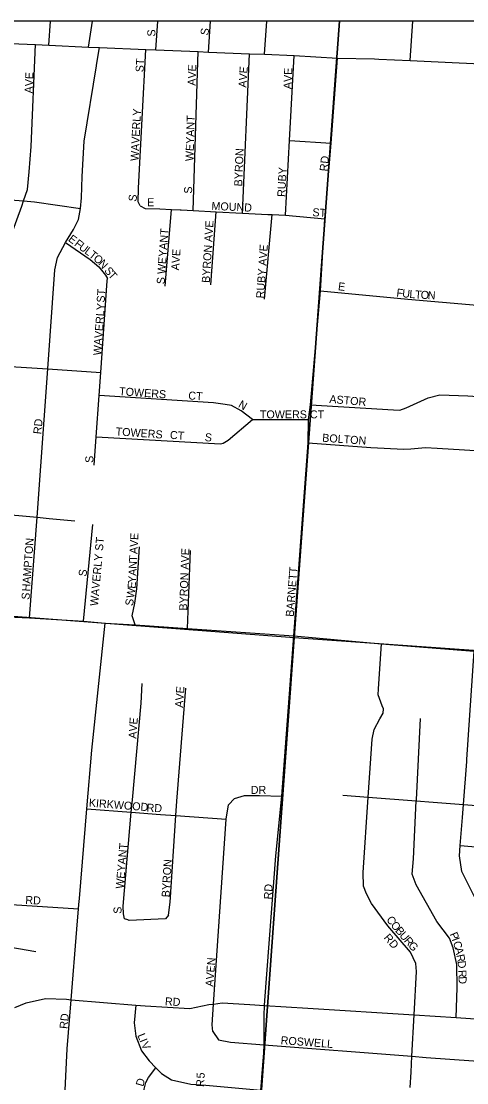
# Model space of a CAD drawing. Extents: x 0 to 34, y 0 to 22.
# Drawn here: x 5.068 to 5.595, y 19.645 to 20.9 of the extents above; entities that cross this region are included whole.
import ezdxf

# ---------------------------------------------------------------- set-up
doc = ezdxf.new("R2010")
doc.units = 0
for name, color, linetype in [('GM_X_City_Street', 7, 'Continuous'), ('GM_X_City_Street_Text', 7, 'Continuous'), ('GM_X_Section', 7, 'Continuous'), ('GM_X_Township', 7, 'Continuous'), ('GM_X_US_Route', 7, 'Continuous')]:
    doc.layers.add(name, color=color, linetype=linetype)

msp = doc.modelspace()

# ---------------------------------------------------------------- linework, layer by layer
at = {"layer": 'GM_X_City_Street'}
for points in [[(5.1011, 20.8716), (5.103, 20.9)], [(5.148, 20.8695), (5.1527, 20.9)], [(5.2275, 20.8662), (5.2299, 20.9)], [(5.2896, 20.8636), (5.2922, 20.9)], [(5.3558, 20.8609), (5.3585, 20.9)], [(5.5281, 20.8535), (5.5313, 20.9)], [(5.0237, 20.292), (5.0238, 20.2924), (5.0259, 20.3188), (5.04, 20.4931), (5.0489, 20.6036), (5.0507, 20.6286), (5.0558, 20.6448), (5.069, 20.6813), (5.0712, 20.6875), (5.076, 20.7008), (5.0777, 20.722), (5.0801, 20.7519), (5.0855, 20.8723)], [(5.1574, 20.8479), (5.1608, 20.8689)], [(5.2092, 20.6818), (5.2067, 20.6864), (5.2072, 20.7027), (5.2158, 20.8667)], [(5.2716, 20.6761), (5.2775, 20.8641)], [(5.3299, 20.6731), (5.3384, 20.8616)], [(5.3806, 20.6705), (5.3854, 20.7588), (5.391, 20.8595)], [(5.3905, 20.173), (5.4075, 20.4012), (5.4079, 20.4289), (5.4104, 20.4465), (5.4222, 20.5812), (5.4271, 20.6663), (5.4348, 20.7558), (5.4421, 20.8564)], [(5.0784, 20.1943), (5.0873, 20.3133), (5.0998, 20.4888), (5.1081, 20.6061), (5.1112, 20.6204), (5.1209, 20.6382), (5.1303, 20.6537), (5.136, 20.6657), (5.1386, 20.6785), (5.1397, 20.691), (5.1405, 20.7164), (5.1428, 20.7581), (5.1573, 20.8472), (5.1574, 20.8479)], [(5.3854, 20.7588), (5.4348, 20.7558)], [(5.0001, 20.6928), (5.0031, 20.6926), (5.0712, 20.6875), (5.0843, 20.6865), (5.1386, 20.6785)], [(5.2092, 20.6818), (5.2148, 20.6786), (5.2322, 20.6781), (5.2459, 20.6774), (5.2563, 20.6768)], [(5.2387, 20.5868), (5.2459, 20.6774)], [(5.2563, 20.6768), (5.2576, 20.6768), (5.2716, 20.6761), (5.2988, 20.6747), (5.3299, 20.6731), (5.3599, 20.6716)], [(5.2925, 20.5882), (5.2988, 20.6747)], [(5.3561, 20.5712), (5.3651, 20.6713)], [(5.3599, 20.6716), (5.3651, 20.6713), (5.3806, 20.6705), (5.4271, 20.6663)], [(5.1209, 20.6382), (5.1498, 20.6183), (5.1601, 20.6095), (5.1682, 20.5998), (5.1703, 20.5959)], [(5.1548, 20.375), (5.1572, 20.4084), (5.1606, 20.4572), (5.1626, 20.4846), (5.1702, 20.5929), (5.1703, 20.5959)], [(5.4222, 20.5812), (5.5255, 20.5713), (5.6571, 20.5599)], [(4.9121, 20.5032), (4.978, 20.498), (5.04, 20.4931), (5.0559, 20.4918), (5.0998, 20.4888), (5.1626, 20.4846)], [(5.3417, 20.4289), (5.3284, 20.4391), (5.3168, 20.4455), (5.3093, 20.4469), (5.2957, 20.4488), (5.1606, 20.4572)], [(5.4104, 20.4465), (5.5085, 20.4404), (5.516, 20.4402), (5.5233, 20.4426), (5.5494, 20.4548), (5.5632, 20.4582), (5.5961, 20.4568), (5.682, 20.4509), (5.694, 20.4472)], [(5.1572, 20.4084), (5.304, 20.4001), (5.3072, 20.4009), (5.3131, 20.4044), (5.3417, 20.4289)], [(5.3417, 20.4289), (5.4079, 20.4289)], [(5.4075, 20.4012), (5.4814, 20.396), (5.5204, 20.3937), (5.5287, 20.3942), (5.5462, 20.396), (5.5598, 20.3952), (5.6892, 20.3872), (5.7426, 20.3839)], [(5.0312, 20.3184), (5.0313, 20.3184), (5.0655, 20.3153), (5.0873, 20.3133), (5.1016, 20.312)], [(5.1016, 20.312), (5.1016, 20.312), (5.1317, 20.3093)], [(5.1422, 20.1904), (5.1532, 20.3048)], [(5.203, 20.1861), (5.1997, 20.1968), (5.2028, 20.2119), (5.2052, 20.2289), (5.2081, 20.2782)], [(5.2651, 20.1817), (5.2686, 20.2742)], [(4.8427, 20.2119), (4.8977, 20.2074), (5.0441, 20.196), (5.0784, 20.1943), (5.1422, 20.1904), (5.1677, 20.188), (5.203, 20.1861), (5.2651, 20.1817), (5.3905, 20.173), (5.4941, 20.1636), (5.6037, 20.1551), (5.6314, 20.1529)], [(5.1372, 19.8624), (5.146, 19.9684), (5.1519, 20.0381), (5.1677, 20.188)], [(5.3527, 19.6506), (5.3551, 19.6798), (5.3556, 19.6896), (5.3556, 19.6904), (5.3556, 19.7242), (5.356, 19.7361), (5.3562, 19.7417), (5.3695, 19.913), (5.3764, 19.9836), (5.3905, 20.173)], [(5.5281, 19.6391), (5.5291, 19.6569), (5.5301, 19.6759), (5.5327, 19.7248), (5.5354, 19.7762), (5.5347, 19.7857), (5.5284, 19.7991), (5.5018, 19.8302), (5.4824, 19.8566), (5.4764, 19.8681), (5.4731, 19.8772), (5.4726, 19.8932), (5.4785, 19.9823), (5.4831, 20.0508), (5.4855, 20.0622), (5.4921, 20.075), (5.4963, 20.0818), (5.4964, 20.0868), (5.4949, 20.0902), (5.4901, 20.1035), (5.4906, 20.1104), (5.4941, 20.1636)], [(5.8036, 19.6561), (5.8045, 19.6679), (5.8027, 19.6797), (5.7979, 19.6904), (5.7943, 19.6956), (5.7919, 19.6992), (5.7787, 19.7066), (5.7353, 19.7265), (5.7202, 19.7346), (5.6977, 19.7437), (5.6829, 19.7593), (5.6398, 19.8127), (5.6095, 19.8533), (5.5891, 19.8946), (5.5863, 19.9128), (5.5872, 19.9251), (5.5898, 19.9584), (5.591, 19.9736), (5.595, 20.0245), (5.5952, 20.0268), (5.6037, 20.1551)], [(5.1944, 19.8371), (5.1903, 19.8384), (5.1892, 19.8445), (5.1889, 19.8536), (5.1985, 19.9644), (5.1998, 19.9793), (5.21, 20.0936), (5.2115, 20.1168)], [(5.2423, 19.8428), (5.2443, 19.858), (5.2513, 19.9605), (5.2525, 19.9776), (5.2631, 20.1113)], [(5.5824, 19.7216), (5.5838, 19.7567), (5.5833, 19.7844), (5.579, 19.8042), (5.5746, 19.8157), (5.5596, 19.8352), (5.535, 19.8788), (5.5306, 19.8914), (5.532, 19.9093), (5.5353, 19.9778), (5.5354, 19.9791), (5.5403, 20.0752)], [(5.295, 19.7051), (5.294, 19.7131), (5.2957, 19.7377), (5.3108, 19.9564), (5.3133, 19.9733), (5.3206, 19.9808), (5.3324, 19.9844), (5.3502, 19.9842), (5.3764, 19.9836)], [(5.4485, 19.9847), (5.4785, 19.9823), (5.5353, 19.9778), (5.5551, 19.9763), (5.591, 19.9736), (5.7406, 19.9624), (5.8253, 19.9567), (5.8774, 19.9551)], [(5.146, 19.9684), (5.1985, 19.9644), (5.2331, 19.9618), (5.2513, 19.9605), (5.3108, 19.9564)], [(4.7017, 19.9438), (4.7265, 19.9132), (4.747, 19.8952), (4.7603, 19.887), (4.7667, 19.883), (4.7883, 19.8719), (4.8065, 19.8688), (4.8195, 19.8677), (4.8649, 19.8637), (4.9119, 19.8608), (4.9286, 19.8597), (4.9851, 19.8558), (4.9916, 19.8566), (5.0026, 19.858), (5.0185, 19.8595), (5.0483, 19.8561), (5.0568, 19.8552), (5.1362, 19.8504)], [(5.5872, 19.9251), (5.6463, 19.9201), (5.734, 19.9127), (5.751, 19.9068), (5.7611, 19.8976), (5.7659, 19.8835), (5.768, 19.8679), (5.7701, 19.8526), (5.7749, 19.8438), (5.7877, 19.8338), (5.8002, 19.8295), (5.8149, 19.8285), (5.8199, 19.8281), (5.8507, 19.8259), (5.8687, 19.8255), (5.8867, 19.8247), (5.9035, 19.8314), (5.9329, 19.8463), (5.9398, 19.8472), (5.9462, 19.848), (5.969, 19.8474), (6.0896, 19.8384), (6.0994, 19.8349), (6.1058, 19.8318)], [(5.0828, 19.1872), (5.0917, 19.2496), (5.0961, 19.3044), (5.107, 19.4367), (5.1165, 19.5549), (5.1227, 19.6848), (5.1274, 19.7428), (5.1341, 19.8264), (5.1362, 19.8504), (5.1365, 19.8552), (5.1372, 19.8624)], [(5.2423, 19.8428), (5.2389, 19.8383), (5.196, 19.8365), (5.1952, 19.8368), (5.1944, 19.8371)], [(5.0448, 19.8068), (5.0859, 19.8)], [(5.061, 19.7336), (5.0744, 19.7392), (5.0971, 19.7441), (5.1221, 19.7433), (5.1274, 19.7428), (5.2038, 19.7363), (5.2149, 19.7354), (5.2676, 19.7322), (5.29, 19.737), (5.2957, 19.7377), (5.3059, 19.7389), (5.3385, 19.7372), (5.356, 19.7361), (5.407, 19.7328), (5.5327, 19.7248), (5.5824, 19.7216), (5.6559, 19.7168)], [(5.2038, 19.7363), (5.2021, 19.7153), (5.2039, 19.6997), (5.2105, 19.6825), (5.2195, 19.6706), (5.2277, 19.6622), (5.2341, 19.6556), (5.2462, 19.6479), (5.2689, 19.6431), (5.2867, 19.6416), (5.3515, 19.6359), (5.3645, 19.6348), (5.4093, 19.6308), (5.4574, 19.6266), (5.4699, 19.6234), (5.4903, 19.6152), (5.4977, 19.6113), (5.5148, 19.6023), (5.539, 19.5949), (5.5768, 19.5906), (5.5986, 19.5908)], [(5.295, 19.7051), (5.3014, 19.6952), (5.3158, 19.6927), (5.3556, 19.6896), (5.5301, 19.6759), (5.5471, 19.6746), (5.7816, 19.6579), (5.8036, 19.6561), (5.8563, 19.6532), (5.8646, 19.6509), (5.9094, 19.6485), (5.9337, 19.6524), (5.952, 19.6575), (5.9667, 19.6584), (5.9676, 19.6585), (6.077, 19.6485), (6.0905, 19.6473), (6.2149, 19.6386), (6.2244, 19.6401), (6.2305, 19.6423), (6.2393, 19.6502)], [(5.2089, 19.5439), (5.2124, 19.6179), (5.2138, 19.6369), (5.2158, 19.6448), (5.2189, 19.6509), (5.2277, 19.6622)], [(5.3291, 19.3335), (5.3322, 19.3716), (5.3361, 19.4196), (5.337, 19.4584), (5.3432, 19.5337), (5.3515, 19.6359), (5.3523, 19.6449), (5.3527, 19.6506)]]:
    msp.add_lwpolyline(points, dxfattribs=at)
at = {"layer": 'GM_X_Section'}
for p, q in [((5.4444, 20.9), (4.9378, 20.9)), ((5.95, 20.9), (5.4444, 20.9))]:
    msp.add_line(p, q, dxfattribs=at)
for points in [[(4.9378, 20.9), (4.8879, 20.2095), (5.3911, 20.1713), (5.4444, 20.9)], [(5.4444, 20.9), (5.3911, 20.1713), (5.8928, 20.1355), (5.95, 20.9)]]:
    msp.add_lwpolyline(points, dxfattribs=at)
for points in [[(4.8879, 20.2095), (5.3911, 20.1713), (5.3184, 19.1674), (4.8168, 19.2029)], [(5.3911, 20.1713), (5.8928, 20.1355), (5.819, 19.1295), (5.3184, 19.1674)]]:
    msp.add_lwpolyline(points, close=True, dxfattribs=at)
at = {"layer": 'GM_X_Township'}
msp.add_lwpolyline([(9.4, 17.8295), (9.4, 20.9), (4.4299, 20.9)], dxfattribs=at)
at = {"layer": 'GM_X_US_Route'}
for points in [[(5.0458, 20.8741), (5.0855, 20.8723), (5.1011, 20.8716), (5.148, 20.8695), (5.1608, 20.8689), (5.2158, 20.8667), (5.2275, 20.8662), (5.2775, 20.8641), (5.2896, 20.8636), (5.3384, 20.8616), (5.3558, 20.8609), (5.391, 20.8595), (5.4421, 20.8564), (5.4861, 20.8554), (5.4912, 20.8551)], [(5.4912, 20.8551), (5.5281, 20.8535), (5.6526, 20.8478), (5.6897, 20.8454), (5.6938, 20.8452), (5.8835, 20.8361), (6.0324, 20.8292), (6.0337, 20.8291), (6.12, 20.8262), (6.3215, 20.8195), (6.3249, 20.8193), (6.4498, 20.8134), (6.5061, 20.8113), (6.5599, 20.8089), (6.616, 20.805), (6.6658, 20.8025), (6.6677, 20.8024), (6.731, 20.7995), (6.7567, 20.7983), (6.8528, 20.7939), (6.8557, 20.7938), (6.9552, 20.7898)]]:
    msp.add_lwpolyline(points, dxfattribs=at)

# ---------------------------------------------------------------- texts
at = {"layer": 'GM_X_City_Street_Text'}
for s, rotation, p in [('S', 82.8783, (5.2895, 20.8829)), ('S', 90, (5.227, 20.8819)), ('ST', 86.4262, (5.2129, 20.8395)), ('AVE', 88.0264, (5.2745, 20.8236)), ('AVE', 86.0569, (5.3345, 20.8212)), ('AVE', 88.0261, (5.3879, 20.8195)), ('AVE', 88.0261, (5.082, 20.8145)), ('WAVERLY', 87.103, (5.207, 20.7345)), ('WEYANT', 88.3643, (5.272, 20.7344)), ('BYRON', 87.664, (5.3295, 20.7045)), ('RD', 83.9946, (5.4304, 20.7221)), ('RUBY', 87.0657, (5.3804, 20.692)), ('S', 90, (5.2704, 20.6961)), ('S', 83.6625, (5.2045, 20.6863)), ('E', 0, (5.2172, 20.6812)), ('MOUND', 357.2278, (5.2931, 20.677)), ('ST', 356.4118, (5.4123, 20.6695)), ('S WEYANT', 85.9708, (5.2379, 20.5887)), ('BYRON AVE', 86.467, (5.2912, 20.5903)), ('E', 322.8296, (5.1232, 20.6408)), ('F', 322.842, (5.1305, 20.6353)), ('U', 322.8434, (5.1358, 20.6312)), ('L', 322.842, (5.1425, 20.6262)), ('T', 321.2335, (5.1477, 20.6222)), ('AVE', 86.0569, (5.255, 20.6051)), ('RUBY AVE', 85.9708, (5.3554, 20.572)), ('O', 319.2233, (5.1529, 20.6181)), ('N', 312.7279, (5.159, 20.6129)), ('S', 308.28, (5.1661, 20.6049)), ('T', 311.0908, (5.1705, 20.5993)), ('E', 352.8783, (5.4424, 20.582)), ('ST', 86.4254, (5.167, 20.567)), ('F', 353.346, (5.5115, 20.5745)), ('U', 354.0112, (5.5183, 20.5737)), ('L', 356.0251, (5.5269, 20.5728)), ('T', 356.3933, (5.5336, 20.5723)), ('O', 356.4123, (5.5403, 20.5719)), ('N', 356.4348, (5.5486, 20.5714)), ('WAVERLY', 85.8545, (5.1629, 20.5045)), ('TOWERS', 355.9842, (5.1839, 20.4578)), ('CT', 355.9166, (5.2656, 20.4528)), ('N', 330.4917, (5.3241, 20.4441)), ('ASTOR', 355.0331, (5.4323, 20.4487)), ('TOWERS CT', 0, (5.3505, 20.4303)), ('RD', 83.9946, (5.092, 20.4112)), ('TOWERS', 355.9842, (5.1798, 20.4103)), ('CT', 355.9166, (5.2439, 20.4062)), ('S', 352.8514, (5.2849, 20.4037)), ('BOLTON', 355.9166, (5.4239, 20.4028)), ('S', 90, (5.1537, 20.3777)), ('HAMPTON', 85.8545, (5.0787, 20.2254)), ('WAVERLY ST', 84.8616, (5.1591, 20.2081)), ('E', 87.1308, (5.2066, 20.2863)), ('A', 87.1331, (5.2058, 20.2697)), ('V', 87.1441, (5.2062, 20.278)), ('BYRON AVE', 87.8801, (5.2645, 20.2028)), ('T', 87.1508, (5.2053, 20.2605)), ('S', 82.8783, (5.1454, 20.2429)), ('A', 87.1331, (5.2045, 20.2439)), ('N', 87.1331, (5.2049, 20.2522)), ('BARNETT', 85.5318, (5.3904, 20.1954)), ('Y', 87.0881, (5.204, 20.2355)), ('W', 81.5044, (5.2018, 20.2172)), ('E', 85.6853, (5.2035, 20.2286)), ('S', 82.8817, (5.0779, 20.2154)), ('S', 81.0004, (5.2004, 20.208)), ('AVE', 85.9166, (5.2595, 20.0879)), ('AVE', 86.0569, (5.2045, 20.0512)), ('DR', 0, (5.3397, 19.9862)), ('KIRKWOOD', 355.544, (5.1481, 19.9712)), ('RD', 356.989, (5.2164, 19.9653)), ('WEYANT', 85.2391, (5.1895, 19.8737)), ('BYRON', 86.4984, (5.2437, 19.8637)), ('RD', 86.989, (5.3646, 19.8612)), ('RD', 356.989, (5.0731, 19.8562)), ('S', 90, (5.187, 19.8444)), ('C', 303.6429, (5.4995, 19.8378)), ('O', 309.7746, (5.5044, 19.8307)), ('B', 310.8846, (5.5098, 19.8241)), ('U', 310.8908, (5.5147, 19.8184)), ('RD', 310.9166, (5.4963, 19.8158)), ('R', 310.8752, (5.5202, 19.8121)), ('P', 293.3134, (5.5745, 19.8203)), ('I', 290.2184, (5.5771, 19.8143)), ('C', 287.2599, (5.5785, 19.8105)), ('G', 311.2414, (5.5251, 19.8064)), ('A', 282.6047, (5.5807, 19.8036)), ('AVEN', 85.6039, (5.2954, 19.7579)), ('R', 281.5147, (5.5825, 19.7955)), ('D', 276.4174, (5.584, 19.7884)), ('R', 271.9431, (5.585, 19.7778)), ('D', 271.8363, (5.5852, 19.7703)), ('RD', 356.9884, (5.2381, 19.7362)), ('RD', 83.9934, (5.123, 19.7079)), ('L', 291.8927, (5.2055, 19.7008)), ('ROSWELL', 355.6702, (5.3748, 19.6903)), ('I', 291.8664, (5.208, 19.6946)), ('V', 295.3015, (5.2098, 19.6902)), ('D', 73.7424, (5.2126, 19.6395)), ('R', 86.8417, (5.2845, 19.6394)), ('5', 86.8272, (5.285, 19.6494))]:
    msp.add_text(s, height=0.00947, rotation=rotation, dxfattribs=at).set_placement(p)

doc.saveas('drawing.dxf')
